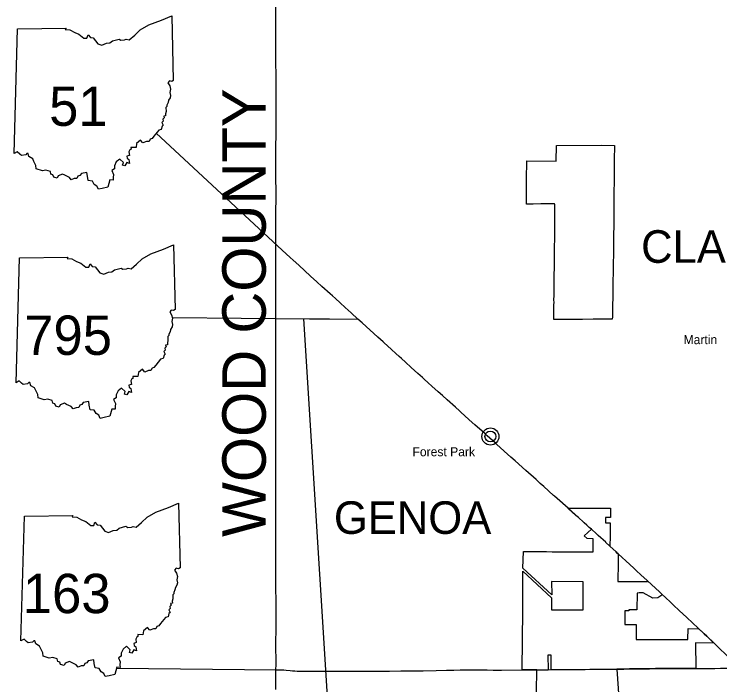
# Model space of a CAD drawing. Extents: x -82 to 873, y 0 to 440.
# Drawn here: x 63 to 144.2, y 176.4 to 253.6 of the extents above; entities that cross this region are included whole.
import ezdxf

# ---------------------------------------------------------------- set-up
doc = ezdxf.new("R2010")
doc.units = 0
for name, color, linetype in [('DV_X_Corp_Line', 7, 'Continuous'), ('GM_P_US_Alignment', 7, 'Continuous'), ('GM_X_Adjacent_County_Text', 7, 'Continuous'), ('GM_X_Corporation_Text', 7, 'Continuous'), ('GM_X_County', 7, 'Continuous'), ('GM_X_Interstate_Route', 7, 'Continuous'), ('PV_P_Text', 7, 'Continuous'), ('SH_Data', 7, 'Continuous')]:
    doc.layers.add(name, color=color, linetype=linetype)

msp = doc.modelspace()

# ---------------------------------------------------------------- linework, layer by layer
at = {"layer": 'DV_X_Corp_Line'}
for points in [[(125.107, 218.485), (125.109, 218.657), (125.112, 219.108), (125.123, 220.155), (125.13, 220.498), (125.129, 220.703), (125.14, 221.276), (125.146, 221.925), (125.148, 222.174), (125.154, 223.053), (125.161, 223.486), (125.182, 224.593), (125.196, 225.781), (125.196, 226.192), (125.195, 226.479), (125.201, 226.765), (125.201, 226.93), (125.206, 227.708), (125.206, 227.955), (125.211, 229.348), (125.22, 231.562), (125.218, 231.671), (125.217, 231.705), (125.216, 231.719), (125.213, 231.743), (125.209, 231.755), (125.206, 231.764), (125.199, 231.776), (125.19, 231.787), (125.173, 231.798), (125.166, 231.803), (125.158, 231.806), (125.146, 231.811), (125.139, 231.814), (125.129, 231.817), (125.113, 231.818), (125.087, 231.821), (125.037, 231.823), (124.414, 231.806), (123.633, 231.793), (122.728, 231.776), (121.952, 231.76), (121.95, 234.615), (121.996, 236.74), (125.377, 236.73), (125.409, 238.537), (130.609, 238.55), (132.079, 238.525), (132.062, 236.841), (132.04, 234.954), (132.039, 234.667), (132.021, 232.861), (132.012, 231.901), (132.01, 231.638), (131.957, 225.846), (131.948, 225.093), (131.934, 224.144), (131.91, 222.687), (131.896, 221.909), (131.896, 221.883), (131.895, 221.786), (131.886, 221.336), (131.881, 220.925), (131.867, 220.269), (131.843, 218.793), (131.841, 218.518), (129.619, 218.517), (128.425, 218.506), (127.209, 218.5), (126.327, 218.494), (125.568, 218.488)], [(124.816, 178.185), (124.81, 178.622), (124.792, 179.865), (124.43, 179.862), (124.452, 178.179)]]:
    msp.add_lwpolyline(points, close=True, dxfattribs=at)
msp.add_lwpolyline([(123.083, 173.099), (123.164, 178.161), (122.597, 178.172), (122.509, 178.17), (121.461, 178.176), (121.549, 185.001), (121.547, 189.533), (124.85, 186.434), (124.829, 185.076), (128.485, 185.076), (128.483, 188.308), (124.859, 188.329), (124.867, 186.794), (121.553, 189.863), (121.631, 191.794), (122.037, 191.788), (122.814, 191.775), (124.282, 191.766), (124.911, 191.76), (126.98, 191.747), (128.175, 191.746), (128.674, 191.743), (128.724, 191.743), (129.634, 191.728), (129.618, 193.259), (128.934, 193.271), (128.583, 193.605), (129.432, 194.35), (129.189, 194.566), (128.912, 194.813), (128.592, 195.101), (128.593, 195.103), (128.519, 195.174), (127.949, 195.707), (126.761, 196.755), (131.628, 196.762), (131.613, 195.711), (131.048, 195.71), (131.039, 195.09), (131.604, 195.087), (131.6, 194.692), (131.59, 193.866), (131.581, 193.336), (131.572, 192.643), (131.569, 192.395), (132.277, 191.74), (132.377, 191.648), (132.517, 191.519), (132.512, 191.356), (132.512, 191.064), (132.499, 190.092), (132.496, 189.874), (132.489, 188.931), (132.477, 188.438), (132.476, 188.342), (135.802, 188.326), (135.872, 188.326), (135.871, 188.413), (137.249, 187.143), (137.295, 187.101), (137.579, 186.841), (137.439, 186.691), (137.059, 186.449), (136.49, 186.397), (135.392, 187.012), (134.924, 187.011), (134.715, 186.985), (134.678, 185.072), (133.739, 185.072), (133.742, 184.959), (133.272, 184.958), (133.272, 183.37), (134.573, 183.371), (134.574, 181.67), (138.053, 181.665), (140.524, 181.656), (140.551, 182.909), (141.753, 182.892), (141.789, 182.891), (142.245, 182.456), (142.415, 182.293), (142.705, 182.021), (143.546, 181.233), (141.402, 181.277), (141.434, 178.319), (141.219, 178.318), (138.632, 178.312), (138.098, 178.305), (137.523, 178.305), (136.825, 178.296), (136.111, 178.282), (134.988, 178.271), (134.687, 178.268), (134.318, 178.262), (134.06, 178.261), (133.813, 178.261), (133.155, 178.251), (132.785, 178.248), (132.377, 178.245), (132.574, 174.91)], dxfattribs=at)
for radius in [0.982, 0.623]:
    msp.add_circle((117.812, 205.025), radius, dxfattribs=at)
at = {"layer": 'GM_P_US_Alignment'}
msp.add_line((93.091, 218.609), (102.571, 218.545), dxfattribs=at)
at = {"layer": 'GM_X_County'}
msp.add_lwpolyline([(93.099, 254.718), (93.102, 252.913), (93.099, 252.134), (93.1, 251.763), (93.103, 251.232), (93.096, 250.371), (93.099, 249.181), (93.104, 245.489), (93.109, 245.161), (93.111, 244.984), (93.117, 244.34), (93.119, 244.134), (93.124, 243.643), (93.122, 243.151), (93.12, 242.331), (93.117, 241.511), (93.113, 241.06), (93.113, 240.444), (93.105, 239.953), (93.098, 238.229), (93.095, 237.696), (93.095, 236.629), (93.1, 235.194), (93.102, 234.579), (93.105, 233.471), (93.105, 232.94), (93.104, 231.921), (93.103, 231.422), (93.101, 230.984), (93.1, 230.479), (93.099, 229.166), (93.096, 228.551), (93.098, 227.853), (93.098, 227.681), (93.1, 227.328), (93.1, 227.169), (93.093, 226.564), (93.094, 225.702), (93.094, 225.473), (93.092, 224.739), (93.088, 224.395), (93.09, 223.955), (93.088, 223.225), (93.083, 222.5), (93.082, 221.934), (93.084, 221.498), (93.083, 221.348), (93.085, 220.989), (93.084, 220.252), (93.084, 219.728), (93.089, 219.212), (93.091, 218.588), (93.086, 218.245), (93.085, 217.795), (93.087, 217.622), (93.086, 217.474), (93.078, 217.041), (93.078, 216.957), (93.078, 216.94), (93.078, 216.438), (93.082, 215.938), (93.081, 215.521), (93.081, 215.429), (93.077, 214.625), (93.078, 213.615), (93.08, 213.312), (93.081, 213.107), (93.078, 212.282), (93.079, 212.06), (93.078, 211.379), (93.076, 210.846), (93.078, 210.386), (93.078, 209.894), (93.081, 209.409), (93.081, 208.51), (93.081, 208.073), (93.081, 207.702), (93.085, 206.861), (93.085, 206.603), (93.086, 206.319), (93.087, 205.998), (93.085, 205.396), (93.086, 204.905), (93.085, 204.599), (93.084, 203.797), (93.086, 202.935), (93.084, 202.566), (93.083, 201.868), (93.083, 200.843), (93.089, 199.694), (93.087, 198.955), (93.089, 198.217), (93.088, 197.56), (93.088, 195.919), (93.088, 194.606), (93.086, 193.416), (93.082, 192.636), (93.084, 192.086), (93.085, 191.98), (93.084, 191.415), (93.084, 191.241), (93.08, 190.589), (93.09, 189.928), (93.095, 188.943), (93.099, 187.918), (93.1, 187.302), (93.105, 186.358), (93.108, 185.415), (93.111, 183.364), (93.104, 182.709), (93.099, 181.436), (93.103, 180.144), (93.106, 179.834), (93.106, 179.424), (93.107, 178.768), (93.103, 178.177), (93.102, 178.029), (93.088, 177.086), (93.075, 175.899)], dxfattribs=at)
at = {"layer": 'GM_X_Interstate_Route'}
for points in [[(102.571, 218.545), (101.775, 219.27), (101.107, 219.877), (100.528, 220.4), (99.981, 220.897), (99.647, 221.2), (99.373, 221.448), (98.434, 222.306), (97.856, 222.829), (97.127, 223.492), (95.759, 224.733), (95.123, 225.315), (94.757, 225.645), (93.848, 226.475), (79.349, 239.926)], [(81.253, 218.712), (96.994, 218.575), (98.596, 218.561), (99.295, 218.554), (102.571, 218.545)], [(117.323, 205.199), (117.114, 205.391), (116.015, 206.378), (115.374, 206.955), (114.825, 207.448), (114.459, 207.78), (114.216, 207.999), (113.819, 208.355), (113.779, 208.391), (112.842, 209.234), (112.293, 209.728), (111.793, 210.18), (111.075, 210.828), (110.648, 211.214), (110.183, 211.638), (109.981, 211.822), (109.465, 212.291), (108.703, 212.979), (108.039, 213.583), (107.579, 214), (107.306, 214.249), (106.943, 214.582), (106.424, 215.048), (105.533, 215.859), (105.483, 215.905), (104.875, 216.457), (103.049, 218.109), (102.571, 218.545)], [(125.187, 198.147), (125.077, 198.246), (123.95, 199.262), (123.554, 199.619), (123.062, 200.054), (121.903, 201.098), (120.648, 202.219), (120.159, 202.658), (119.794, 202.988), (118.538, 204.108), (118.352, 204.275), (117.421, 205.109), (117.405, 205.123), (117.323, 205.199)], [(126.76, 196.737), (126.74, 196.755), (125.479, 197.884), (125.187, 198.147)], [(127.648, 195.946), (126.76, 196.737)], [(129.321, 194.449), (129.189, 194.566), (128.912, 194.813), (128.592, 195.101), (128.515, 195.17), (127.934, 195.692), (127.648, 195.946)], [(131.083, 192.84), (130.23, 193.623), (130.113, 193.729), (130.021, 193.812), (129.443, 194.34), (129.333, 194.438), (129.321, 194.449)], [(131.569, 192.395), (131.085, 192.839), (131.083, 192.84)], [(135.83, 188.449), (135.803, 188.471), (135.176, 189.041), (134.579, 189.601), (134.308, 189.852), (133.859, 190.271), (132.517, 191.519), (132.377, 191.648), (132.277, 191.74), (131.569, 192.395)], [(137.249, 187.143), (135.871, 188.413), (135.83, 188.449)], [(137.483, 186.929), (137.449, 186.96), (137.295, 187.101), (137.249, 187.143)], [(141.722, 182.953), (140.424, 184.172), (139.528, 185.01), (138.872, 185.625), (138.546, 185.935), (137.948, 186.491), (137.579, 186.841), (137.483, 186.929)], [(143.449, 181.324), (142.705, 182.021), (142.415, 182.293), (142.245, 182.456), (141.866, 182.817), (141.789, 182.891), (141.762, 182.915), (141.722, 182.953)], [(146.548, 178.353), (146.523, 178.377), (146.166, 178.724), (145.614, 179.254), (145.028, 179.812), (144.75, 180.079), (144.343, 180.47), (143.892, 180.895), (143.546, 181.233), (143.505, 181.272), (143.449, 181.324)], [(74.793, 178.357), (93.212, 178.176), (93.541, 178.173), (93.786, 178.168), (94.032, 178.155), (94.318, 178.13), (94.766, 178.078), (95.052, 178.048), (95.298, 178.03), (95.586, 178.019), (95.997, 178.015), (97.228, 178.019), (98.09, 178.015), (98.788, 178.019), (101.456, 178.018), (102.852, 178.02), (103.467, 178.02), (104.879, 178.02), (105.274, 178.02), (106.218, 178.02), (107.49, 178.032), (108.64, 178.047), (109.378, 178.052), (110.076, 178.063), (111.554, 178.083), (112.744, 178.112), (113.606, 178.138), (114.344, 178.156), (114.878, 178.164), (115.822, 178.159), (116.355, 178.155), (117.422, 178.144), (118.142, 178.141), (119.081, 178.141), (121.461, 178.15), (121.467, 178.15)], [(121.467, 178.15), (122.509, 178.157), (122.597, 178.157), (123.074, 178.161)], [(123.074, 178.161), (123.097, 178.161), (123.164, 178.161), (123.35, 178.162), (123.949, 178.169), (124.399, 178.179)], [(124.399, 178.179), (124.401, 178.179), (124.452, 178.179), (124.764, 178.186), (124.794, 178.186)], [(124.794, 178.186), (124.816, 178.185), (125.047, 178.191), (125.11, 178.193), (125.582, 178.197), (125.597, 178.197), (126.199, 178.199), (126.567, 178.202), (126.61, 178.203), (127.267, 178.204), (127.537, 178.207), (127.761, 178.209), (128.404, 178.214), (128.514, 178.215), (128.729, 178.216), (129.264, 178.22), (129.48, 178.222), (130.449, 178.23), (130.994, 178.234), (131.285, 178.233), (131.417, 178.236), (131.756, 178.24), (132.377, 178.245), (132.785, 178.248), (133.155, 178.251), (133.813, 178.261), (134.06, 178.261), (134.318, 178.262), (134.687, 178.268), (134.988, 178.271), (136.111, 178.282), (136.111, 178.282)], [(136.111, 178.282), (136.825, 178.296), (137.523, 178.305), (138.098, 178.305), (138.632, 178.312), (141.219, 178.318), (141.434, 178.319), (141.437, 178.319)], [(141.437, 178.319), (143.641, 178.332), (144.298, 178.338), (144.728, 178.343), (145.621, 178.347), (146.548, 178.353)]]:
    msp.add_lwpolyline(points, dxfattribs=at)
at = {"layer": 'PV_P_Text'}
for p, q in [((63.009, 237.583), (63.409, 251.946)), ((63.009, 237.583), (63.409, 251.946)), ((63.23, 211.216), (63.63, 225.579)), ((63.23, 211.216), (63.63, 225.579)), ((63.799, 181.483), (64.199, 195.845)), ((63.799, 181.483), (64.199, 195.845))]:
    msp.add_line(p, q, dxfattribs=at)
for points in [[(63.409, 251.946), (68.982, 252.04), (68.895, 251.866), (69.421, 251.83), (69.979, 251.523), (70.452, 251.329), (71.03, 250.873), (71.375, 250.878), (71.521, 251.252), (71.786, 250.963), (72.101, 250.912), (72.644, 250.224), (73.092, 250.075), (73.629, 250.311), (74.031, 250.35), (74.324, 250.583), (75.089, 250.782), (75.302, 250.663), (75.707, 250.687), (75.911, 250.775), (76.264, 250.696), (76.886, 251.219), (77.525, 251.834), (78.509, 252.416), (79.979, 252.966), (81.142, 253.459), (81.31, 246.005)], [(63.409, 251.946), (68.982, 252.04), (68.895, 251.866), (69.421, 251.83), (69.979, 251.523), (70.452, 251.329), (71.03, 250.873), (71.375, 250.878), (71.521, 251.252), (71.786, 250.963), (72.101, 250.912), (72.644, 250.224), (73.092, 250.075), (73.629, 250.311), (74.031, 250.35), (74.324, 250.583), (75.089, 250.782), (75.302, 250.663), (75.707, 250.687), (75.911, 250.775), (76.264, 250.696), (76.886, 251.219), (77.525, 251.834), (78.509, 252.416), (79.979, 252.966), (81.142, 253.459), (81.31, 246.005)], [(81.31, 246.005), (81.139, 245.901), (80.872, 245.95), (80.692, 245.741), (80.914, 245.392), (81.019, 245.023), (80.926, 244.617), (81.018, 244.282), (80.956, 244.002), (80.788, 243.723), (80.73, 243.457), (80.588, 243.176), (80.599, 243.02), (80.463, 242.895), (80.488, 242.429), (80.419, 242.171), (80.443, 241.948), (80.222, 241.89), (80.273, 241.705), (80.133, 241.563), (80.163, 241.318), (80.003, 241.162), (80.158, 240.85), (80.034, 240.751), (79.931, 240.37), (79.648, 240.293), (79.081, 239.597), (78.881, 239.335), (78.657, 239.269), (78.533, 238.999), (78.256, 238.998), (77.838, 238.811), (77.567, 239.133), (77.093, 238.745), (77.038, 238.297), (76.439, 238.311), (76.462, 238.085), (76.328, 238.019), (76.207, 237.792), (76.277, 237.389), (75.997, 237.286), (76.031, 237.052), (76.211, 236.909), (76.29, 236.462), (75.992, 236.553), (75.748, 236.176), (75.497, 236.264), (75.579, 236.583), (75.154, 236.967), (74.753, 236.66), (74.543, 236.168), (74.541, 235.838), (74.242, 235.638), (74.434, 235.171), (74.399, 234.849), (74.404, 234.543), (74.03, 234.554), (73.804, 233.73)], [(81.31, 246.005), (81.139, 245.901), (80.872, 245.95), (80.692, 245.741), (80.914, 245.392), (81.019, 245.023), (80.926, 244.617), (81.018, 244.282), (80.956, 244.002), (80.788, 243.723), (80.73, 243.457), (80.588, 243.176), (80.599, 243.02), (80.463, 242.895), (80.488, 242.429), (80.419, 242.171), (80.443, 241.948), (80.222, 241.89), (80.273, 241.705), (80.133, 241.563), (80.163, 241.318), (80.003, 241.162), (80.158, 240.85), (80.034, 240.751), (79.931, 240.37), (79.648, 240.293), (79.081, 239.597), (78.881, 239.335), (78.657, 239.269), (78.533, 238.999), (78.256, 238.998), (77.838, 238.811), (77.567, 239.133), (77.093, 238.745), (77.038, 238.297), (76.439, 238.311), (76.462, 238.085), (76.328, 238.019), (76.207, 237.792), (76.277, 237.389), (75.997, 237.286), (76.031, 237.052), (76.211, 236.909), (76.29, 236.462), (75.992, 236.553), (75.748, 236.176), (75.497, 236.264), (75.579, 236.583), (75.154, 236.967), (74.753, 236.66), (74.543, 236.168), (74.541, 235.838), (74.242, 235.638), (74.434, 235.171), (74.399, 234.849), (74.404, 234.543), (74.03, 234.554), (73.804, 233.73)], [(73.804, 233.73), (73.154, 233.572), (72.702, 233.477), (72.543, 233.852), (72.22, 234.049), (72.01, 234.427), (71.546, 234.478), (71.436, 234.996), (71.385, 235.416), (70.751, 235.312), (70.577, 235.055), (70.352, 234.986), (70.222, 234.727), (69.915, 234.706), (69.586, 234.584), (69.371, 234.837), (68.832, 235.092), (68.59, 235.224), (68.084, 235.02), (67.976, 234.778), (67.573, 234.884), (67.478, 235.154), (67.234, 235.235), (67.18, 235.521), (66.659, 235.673), (66.26, 235.613), (65.556, 235.843), (65.514, 236.219), (65.274, 236.678), (65.149, 236.996), (64.704, 237.239), (64.614, 237.618), (64.472, 237.607), (64.342, 237.453), (63.848, 237.383), (63.65, 237.537), (63.374, 237.801), (63.009, 237.583)], [(73.804, 233.73), (73.154, 233.572), (72.702, 233.477), (72.543, 233.852), (72.22, 234.049), (72.01, 234.427), (71.546, 234.478), (71.436, 234.996), (71.385, 235.416), (70.751, 235.312), (70.577, 235.055), (70.352, 234.986), (70.222, 234.727), (69.915, 234.706), (69.586, 234.584), (69.371, 234.837), (68.832, 235.092), (68.59, 235.224), (68.084, 235.02), (67.976, 234.778), (67.573, 234.884), (67.478, 235.154), (67.234, 235.235), (67.18, 235.521), (66.659, 235.673), (66.26, 235.613), (65.556, 235.843), (65.514, 236.219), (65.274, 236.678), (65.149, 236.996), (64.704, 237.239), (64.614, 237.618), (64.472, 237.607), (64.342, 237.453), (63.848, 237.383), (63.65, 237.537), (63.374, 237.801), (63.009, 237.583)], [(63.63, 225.579), (69.203, 225.673), (69.116, 225.499), (69.642, 225.463), (70.2, 225.156), (70.673, 224.962), (71.25, 224.506), (71.596, 224.511), (71.742, 224.885), (72.007, 224.596), (72.321, 224.545), (72.865, 223.857), (73.313, 223.708), (73.85, 223.944), (74.252, 223.983), (74.545, 224.216), (75.31, 224.415), (75.523, 224.296), (75.928, 224.32), (76.132, 224.408), (76.485, 224.329), (77.106, 224.852), (77.746, 225.467), (78.73, 226.049), (80.2, 226.599), (81.363, 227.092), (81.531, 219.638)], [(63.63, 225.579), (69.203, 225.673), (69.116, 225.499), (69.642, 225.463), (70.2, 225.156), (70.673, 224.962), (71.25, 224.506), (71.596, 224.511), (71.742, 224.885), (72.007, 224.596), (72.321, 224.545), (72.865, 223.857), (73.313, 223.708), (73.85, 223.944), (74.252, 223.983), (74.545, 224.216), (75.31, 224.415), (75.523, 224.296), (75.928, 224.32), (76.132, 224.408), (76.485, 224.329), (77.106, 224.852), (77.746, 225.467), (78.73, 226.049), (80.2, 226.599), (81.363, 227.092), (81.531, 219.638)], [(81.531, 219.638), (81.36, 219.534), (81.093, 219.583), (80.913, 219.374), (81.135, 219.025), (81.24, 218.656), (81.147, 218.25), (81.239, 217.915), (81.177, 217.635), (81.009, 217.356), (80.951, 217.09), (80.808, 216.809), (80.82, 216.653), (80.684, 216.528), (80.709, 216.062), (80.64, 215.804), (80.664, 215.581), (80.443, 215.523), (80.494, 215.338), (80.353, 215.196), (80.383, 214.951), (80.224, 214.795), (80.379, 214.483), (80.255, 214.384), (80.152, 214.003), (79.869, 213.926), (79.302, 213.23), (79.102, 212.968), (78.877, 212.902), (78.754, 212.632), (78.477, 212.631), (78.059, 212.444), (77.788, 212.766), (77.314, 212.378), (77.259, 211.93), (76.66, 211.944), (76.683, 211.718), (76.549, 211.652), (76.427, 211.425), (76.498, 211.022), (76.218, 210.919), (76.252, 210.685), (76.432, 210.542), (76.511, 210.095), (76.213, 210.186), (75.969, 209.809), (75.718, 209.897), (75.8, 210.216), (75.375, 210.6), (74.974, 210.293), (74.764, 209.801), (74.762, 209.471), (74.463, 209.271), (74.655, 208.804), (74.619, 208.482), (74.625, 208.176), (74.251, 208.187), (74.025, 207.362)], [(81.531, 219.638), (81.36, 219.534), (81.093, 219.583), (80.913, 219.374), (81.135, 219.025), (81.24, 218.656), (81.147, 218.25), (81.239, 217.915), (81.177, 217.635), (81.009, 217.356), (80.951, 217.09), (80.808, 216.809), (80.82, 216.653), (80.684, 216.528), (80.709, 216.062), (80.64, 215.804), (80.664, 215.581), (80.443, 215.523), (80.494, 215.338), (80.353, 215.196), (80.383, 214.951), (80.224, 214.795), (80.379, 214.483), (80.255, 214.384), (80.152, 214.003), (79.869, 213.926), (79.302, 213.23), (79.102, 212.968), (78.877, 212.902), (78.754, 212.632), (78.477, 212.631), (78.059, 212.444), (77.788, 212.766), (77.314, 212.378), (77.259, 211.93), (76.66, 211.944), (76.683, 211.718), (76.549, 211.652), (76.427, 211.425), (76.498, 211.022), (76.218, 210.919), (76.252, 210.685), (76.432, 210.542), (76.511, 210.095), (76.213, 210.186), (75.969, 209.809), (75.718, 209.897), (75.8, 210.216), (75.375, 210.6), (74.974, 210.293), (74.764, 209.801), (74.762, 209.471), (74.463, 209.271), (74.655, 208.804), (74.619, 208.482), (74.625, 208.176), (74.251, 208.187), (74.025, 207.362)], [(74.025, 207.362), (73.374, 207.205), (72.923, 207.11), (72.764, 207.485), (72.441, 207.682), (72.231, 208.06), (71.767, 208.111), (71.657, 208.629), (71.605, 209.049), (70.972, 208.945), (70.798, 208.688), (70.573, 208.619), (70.442, 208.36), (70.136, 208.339), (69.807, 208.217), (69.592, 208.47), (69.053, 208.725), (68.811, 208.857), (68.305, 208.653), (68.197, 208.411), (67.794, 208.517), (67.699, 208.787), (67.455, 208.868), (67.401, 209.154), (66.88, 209.306), (66.481, 209.246), (65.777, 209.476), (65.735, 209.852), (65.495, 210.311), (65.37, 210.629), (64.925, 210.872), (64.835, 211.251), (64.693, 211.24), (64.563, 211.086), (64.069, 211.016), (63.871, 211.17), (63.595, 211.434), (63.23, 211.216)], [(74.025, 207.362), (73.374, 207.205), (72.923, 207.11), (72.764, 207.485), (72.441, 207.682), (72.231, 208.06), (71.767, 208.111), (71.657, 208.629), (71.605, 209.049), (70.972, 208.945), (70.798, 208.688), (70.573, 208.619), (70.442, 208.36), (70.136, 208.339), (69.807, 208.217), (69.592, 208.47), (69.053, 208.725), (68.811, 208.857), (68.305, 208.653), (68.197, 208.411), (67.794, 208.517), (67.699, 208.787), (67.455, 208.868), (67.401, 209.154), (66.88, 209.306), (66.481, 209.246), (65.777, 209.476), (65.735, 209.852), (65.495, 210.311), (65.37, 210.629), (64.925, 210.872), (64.835, 211.251), (64.693, 211.24), (64.563, 211.086), (64.069, 211.016), (63.871, 211.17), (63.595, 211.434), (63.23, 211.216)], [(64.199, 195.845), (69.772, 195.94), (69.685, 195.766), (70.211, 195.729), (70.769, 195.423), (71.242, 195.229), (71.82, 194.772), (72.165, 194.778), (72.312, 195.152), (72.576, 194.863), (72.891, 194.811), (73.434, 194.124), (73.882, 193.975), (74.419, 194.211), (74.821, 194.25), (75.114, 194.483), (75.879, 194.682), (76.092, 194.562), (76.497, 194.587), (76.701, 194.675), (77.054, 194.596), (77.676, 195.118), (78.315, 195.734), (79.299, 196.315), (80.769, 196.866), (81.932, 197.358), (82.1, 189.905)], [(64.199, 195.845), (69.772, 195.94), (69.685, 195.766), (70.211, 195.729), (70.769, 195.423), (71.242, 195.229), (71.82, 194.772), (72.165, 194.778), (72.312, 195.152), (72.576, 194.863), (72.891, 194.811), (73.434, 194.124), (73.882, 193.975), (74.419, 194.211), (74.821, 194.25), (75.114, 194.483), (75.879, 194.682), (76.092, 194.562), (76.497, 194.587), (76.701, 194.675), (77.054, 194.596), (77.676, 195.118), (78.315, 195.734), (79.299, 196.315), (80.769, 196.866), (81.932, 197.358), (82.1, 189.905)], [(82.1, 189.905), (81.929, 189.8), (81.662, 189.849), (81.482, 189.64), (81.704, 189.292), (81.809, 188.923), (81.716, 188.517), (81.808, 188.182), (81.746, 187.901), (81.578, 187.623), (81.52, 187.356), (81.377, 187.076), (81.389, 186.919), (81.253, 186.795), (81.278, 186.329), (81.209, 186.071), (81.233, 185.848), (81.012, 185.789), (81.063, 185.605), (80.923, 185.463), (80.952, 185.218), (80.793, 185.062), (80.948, 184.75), (80.824, 184.65), (80.721, 184.27), (80.438, 184.193), (79.871, 183.497), (79.671, 183.234), (79.447, 183.169), (79.323, 182.899), (79.046, 182.897), (78.628, 182.71), (78.357, 183.033), (77.883, 182.645), (77.828, 182.197), (77.229, 182.211), (77.252, 181.985), (77.119, 181.919), (76.997, 181.692), (77.067, 181.289), (76.787, 181.186), (76.821, 180.952), (77.001, 180.809), (77.08, 180.362), (76.782, 180.452), (76.538, 180.075), (76.287, 180.164), (76.369, 180.483), (75.944, 180.867), (75.543, 180.559), (75.333, 180.068), (75.331, 179.737), (75.032, 179.537), (75.224, 179.07), (75.189, 178.749), (75.194, 178.443), (74.82, 178.454), (74.594, 177.629)], [(82.1, 189.905), (81.929, 189.8), (81.662, 189.849), (81.482, 189.64), (81.704, 189.292), (81.809, 188.923), (81.716, 188.517), (81.808, 188.182), (81.746, 187.901), (81.578, 187.623), (81.52, 187.356), (81.377, 187.076), (81.389, 186.919), (81.253, 186.795), (81.278, 186.329), (81.209, 186.071), (81.233, 185.848), (81.012, 185.789), (81.063, 185.605), (80.923, 185.463), (80.952, 185.218), (80.793, 185.062), (80.948, 184.75), (80.824, 184.65), (80.721, 184.27), (80.438, 184.193), (79.871, 183.497), (79.671, 183.234), (79.447, 183.169), (79.323, 182.899), (79.046, 182.897), (78.628, 182.71), (78.357, 183.033), (77.883, 182.645), (77.828, 182.197), (77.229, 182.211), (77.252, 181.985), (77.119, 181.919), (76.997, 181.692), (77.067, 181.289), (76.787, 181.186), (76.821, 180.952), (77.001, 180.809), (77.08, 180.362), (76.782, 180.452), (76.538, 180.075), (76.287, 180.164), (76.369, 180.483), (75.944, 180.867), (75.543, 180.559), (75.333, 180.068), (75.331, 179.737), (75.032, 179.537), (75.224, 179.07), (75.189, 178.749), (75.194, 178.443), (74.82, 178.454), (74.594, 177.629)], [(74.594, 177.629), (73.943, 177.472), (73.492, 177.377), (73.333, 177.752), (73.01, 177.949), (72.8, 178.326), (72.336, 178.378), (72.226, 178.895), (72.174, 179.316), (71.541, 179.212), (71.367, 178.955), (71.142, 178.886), (71.012, 178.627), (70.705, 178.605), (70.376, 178.483), (70.161, 178.737), (69.622, 178.992), (69.38, 179.124), (68.874, 178.919), (68.766, 178.677), (68.363, 178.784), (68.268, 179.054), (68.024, 179.135), (67.97, 179.421), (67.449, 179.573), (67.05, 179.512), (66.346, 179.743), (66.304, 180.119), (66.064, 180.578), (65.939, 180.896), (65.494, 181.139), (65.404, 181.518), (65.262, 181.507), (65.132, 181.353), (64.638, 181.282), (64.441, 181.437), (64.164, 181.701), (63.799, 181.483)], [(74.594, 177.629), (73.943, 177.472), (73.492, 177.377), (73.333, 177.752), (73.01, 177.949), (72.8, 178.326), (72.336, 178.378), (72.226, 178.895), (72.174, 179.316), (71.541, 179.212), (71.367, 178.955), (71.142, 178.886), (71.012, 178.627), (70.705, 178.605), (70.376, 178.483), (70.161, 178.737), (69.622, 178.992), (69.38, 179.124), (68.874, 178.919), (68.766, 178.677), (68.363, 178.784), (68.268, 179.054), (68.024, 179.135), (67.97, 179.421), (67.449, 179.573), (67.05, 179.512), (66.346, 179.743), (66.304, 180.119), (66.064, 180.578), (65.939, 180.896), (65.494, 181.139), (65.404, 181.518), (65.262, 181.507), (65.132, 181.353), (64.638, 181.282), (64.441, 181.437), (64.164, 181.701), (63.799, 181.483)]]:
    msp.add_lwpolyline(points, dxfattribs=at)
at = {"layer": 'SH_Data'}
msp.add_line((100.412, 153.623), (96.328, 218.587), dxfattribs=at)

# ---------------------------------------------------------------- texts
at = {"layer": 'DV_X_Corp_Line'}
for s, height, p in [('Martin', 1.0417, (140.041, 215.653)), ('Forest Park', 1.04167, (108.846, 202.748))]:
    msp.add_text(s, height=height, rotation=0.00501, dxfattribs=at).set_placement(p)
at = {"layer": 'GM_X_Adjacent_County_Text'}
msp.add_text('WOOD COUNTY', height=5, rotation=90.005, dxfattribs=at).set_placement((91.967, 193.465))
at = {"layer": 'GM_X_Corporation_Text'}
for s, p in [('CLAY CENTER', (135.152, 225.017)), ('GENOA', (99.802, 193.81))]:
    msp.add_text(s, height=3.75, rotation=0.00501, dxfattribs=at).set_placement(p)
at = {"layer": 'PV_P_Text'}
for s, p in [('51', (67.035, 240.786)), ('795', (64.169, 214.419)), ('163', (64.006, 184.686))]:
    msp.add_text(s, height=4.5281, rotation=0.005, dxfattribs=at).set_placement(p)

doc.saveas('drawing.dxf')
